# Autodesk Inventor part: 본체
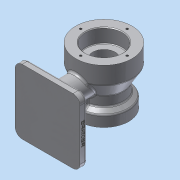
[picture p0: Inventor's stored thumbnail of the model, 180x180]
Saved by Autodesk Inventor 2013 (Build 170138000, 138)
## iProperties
Created: 2019-01
Part Number: 본체
Material: 알루미늄 6061
Document SubType Name: Modeling
Designer: Administrator
Density: 1 g/cm^3
Author: Administrator
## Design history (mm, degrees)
sketch "스케치2"
  geometry: L1 (0, 40)-(0, -40); L2 (0, 40)-(40, 40); L3 (40, 40)-(40, 15); L4 (0, -40)-(35, -40); L5 (35, -40)-(35, -25); L6 (35, -25)-(28, -19.126); L7 (28, -5.785)-(40, 15); L8 (28, -5.785)-(28, -19.126); 2 further points
  constraints: 16 end point, 4 perpendicular, 1 coincident, 1 midpoint
  dimensions: "d6" = 80 distance of L1.start L1.end; "d7" = 40 distance of L1.start L2.end; "d8" = 25 distance of L2.end L3.end; "d9" = 35 distance of L1.end L4.end; "d10" = 15 distance of L4.end L5.end; "d14" = 20.78461 vertical distance of L7.start L3.end; "d15" = 13.34169 distance of L7.start L6.end; "d16" = 5.8737 vertical distance of L5.end L6.end; "d17" = 30 deg angle of L8 L7; "d18" = 130 deg angle of L6 L8
revolve "회전1" sketch "스케치2" stored, may be unused: angle "d19" = 90 deg
hole "구멍1" diameter "d22" = 52; stored, may be unused: countersink angle "d26" = 90 deg, drill point angle "d28" = 0 deg; dims "d20" = 10, "d21" = 10, "d23" = 6, "d24" = 4, "d25" = 2, "d27" = 20
hole "구멍2" diameter "d31" = 40; stored, may be unused: countersink angle "d35" = 90 deg, drill point angle "d37" = 0 deg; dims "d29" = 10, "d30" = 10, "d32" = 6, "d33" = 4, "d34" = 2, "d36" = 17
hole "구멍3" diameter "d40" = 32; stored, may be unused: countersink angle "d44" = 90 deg, drill point angle "d46" = 0 deg; dims "d38" = 10, "d39" = 10, "d41" = 6, "d42" = 4, "d43" = 2, "d45" = 17
chamfer "모따기1" distance "d47" = 1; stored, may be unused: second distance "d48" = 2, angle "d49" = 45 deg
sketch "스케치3"
  geometry: L1 (-40, 40)-(40, 40) reference; L2 (-80, 35)-(-80, -57); L3 (-80, -57)-(-70, -57); L4 (-80, 35)-(-70, 35); L5 (-70, 35)-(-70, -57); L6 (-28, -5.785)-(-28, -19.126) reference; 1 further point
  constraints: 8 end point, 2 perpendicular, 1 parallel
  dimensions: "d53" = 92 distance of L2.start L2.end; "d54" = 10 distance of L2.end L3.end; "d55" = 10 distance of L2.start L4.end; "d56" = 5 distance from line of L1 L4.end; "d57" = 42 distance from line of L3.end L6
extrude "돌출2" join sketch "스케치3" stored distance "d58" = 92; taper "d59" = 0 deg
fillet "모깎기2" dims "d60" = 10
sketch "스케치4"
  geometry: L1 (82, 82)-(82, 10) reference; L2 (31, 45.199)-(31, 82); L3 (41, 45.199)-(41, 82); L4 (31, 82)-(41, 82); A1 r 10 centre (72, 10) between (72, 0) and (82, 10) reference; A2 r 16 centre (36, 30) between (31, 45.199) and (41, 45.199); 1 further point
  constraints: 6 end point, 3 parallel, 2 point on circle, 1 centre point, 1 perpendicular
  dimensions: "d62" = 32 diameter of A2; "d67" = 36.80132 distance of L3.start L3.end; "d68" = 10 distance of L2.end L3.end; "d69" = 31 distance from line of A1.centre L3; "d70" = 35.19868 vertical distance of A1.centre L3.start
extrude "돌출3" join sketch "스케치4" stored distance "d71" = 92; taper "d72" = 0 deg
feature "면 기울기1" dims angle "d73" = 25 deg
sketch "스케치5" dims "d74" = 66
  geometry: C1 r 27 at (0, 0) reference; 2 further points
  constraints: 1 coincident, 1 vertical alignment, 2 other
hole "구멍4" sketch "스케치5" at (0, 33) diameter "d75" = 3.242; stored, may be unused: countersink angle "d79" = 90 deg, drill point angle "d81" = 118 deg; dims "d76" = 9, "d77" = 4, "d78" = 2, "d80" = 11
sketch "스케치6" dims "d85" = 55
  geometry: C1 r 21 at (0, 0) reference; 2 further points
  constraints: 1 coincident, 1 vertical alignment, 2 other
hole "구멍5" sketch "스케치6" at (0, 27.5) diameter "d86" = 3.242; stored, may be unused: countersink angle "d90" = 90 deg, drill point angle "d92" = 118 deg; dims "d87" = 9, "d88" = 4, "d89" = 2, "d91" = 11
fillet "모깎기3" dims "d96" = 1
fillet "모깎기4" dims "d97" = 0.6
fillet "모깎기5" dims "d98" = 3
fillet "모깎기8" dims "d101" = 3
fillet "모깎기9" dims "d102" = 3
node "작업 평면1"
sketch "스케치7"
  geometry: L1 (-80, 25)-(-80, -47) reference; L2 (-73, 35)-(-80, 35) reference; 2 further points
  constraints: 1 other
  dimensions: "d104" = 4 distance from line of point (-76, -11) L1; "d105" = 46 distance from line of L2 point (-76, -11)
feature "엠보싱1" sketch "스케치7" dims "d6" = 80, "d7" = 40, "d8" = 25, "d9" = 35, "d10" = 15, "d14" = 20.78461, "d15" = 13.34169, "d16" = 5.8737, "d17" = 30 deg, "d18" = 130 deg, "d106" = 0.5, "d107" = 0
node "솔리드2"
pattern_circular "원형 패턴1" dims angle "d83" = 360 deg
pattern_circular "원형 패턴2" dims angle "d94" = 360 deg
